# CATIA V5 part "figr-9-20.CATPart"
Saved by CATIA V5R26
Part number: Part3
Bounding box of the stored display mesh (mm): x -112 to 0, y -101.683 to 100, z -80.304 to 44.415
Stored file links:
  D:\_Deepak\CATIA\CATIA V5-6R2016_Deepak\Resources\Part files\Partfiles\c09_catia_v5_6r2016_prt\figr-9-20.CATPart
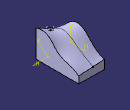
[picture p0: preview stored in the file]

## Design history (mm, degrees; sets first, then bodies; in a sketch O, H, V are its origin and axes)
Set1
  Plane1: type Offset, RefPlane yz-plane, Offset -112
  Plane2: type Offset, RefPlane yz-plane, Offset -63
  Plane3: type Normal, Curve Sketch4, RefPoint vertex of Sketch4
Body1 (main body)
  Sketch1 on yz-plane, origin (0, 0, 0), H (0, 1, 0), V (0, 0, 1)
    spline S1 through (-92.6897, 40.1119) (-30, 30) (10, -10) (60, -30) (97.3103, -50.3041)
    line L1 (97.3103, -50.3041) -> (97.3103, -80.3041)
    line L2 (97.3103, -80.3041) -> (-92.6897, -80.3041)
    line L3 (-92.6897, -80.3041) -> (-92.6897, 40.1119)
    point P3 (-92.6897, 40.1119)
    point P4 (97.3103, -50.3041)
    point P5 (-92.6897, 40.1119)
    point P6 (97.3103, -50.3041)
    vertical: L1 V, L3 V
    horizontal: L2 H
    coincidence: P5 P3, P6 P4
  Sketch2 on Plane1, origin (-112, 0, 0), H (0, 1, 0), V (0, 0, 1)
    spline S1 through (-90, -30) (-70, 10) (-20, 40) (40, 0) (100, -40)
    line L1 (100, -40) -> (100, -80)
    line L2 (100, -80) -> (-90, -80)
    line L3 (-90, -80) -> (-90, -30)
    point P3 (-90, -30)
    point P4 (100, -40)
    point P5 (40, 0)
    point P6 (-90, -30)
    point P7 (100, -40)
    coincidence: P5 H, P6 P3, P7 P4
    vertical: L1 V, L3 V
    horizontal: L2 H
  Loft1: Sections (Sketch1; Sketch2)
  Sketch3 on Plane3, origin (0, -40.1726, -44.9298), H (1, 0, 0), V (0, -0.7455, 0.6665)
    point P1 (-63, 68.4187)
    line L1 (-63, 68.4187) -> (-75.2117, 62.4925)
    line L2 (-75.2117, 62.4925) -> (-79.6266, 71.5898)
    line L3 (-79.6266, 71.5898) -> (-57.1205, 82.5119)
    line L4 (-57.1205, 82.5119) -> (-52.7056, 73.4145)
    point P5 (-52.7056, 73.4145)
    line L5 (-52.7056, 73.4145) -> (-63, 68.4187)
    reference projected point E1 (-63, 68.4187) from vertex of Sketch4
    perpendicularity: L2 L1
    parallelism: L3 L1, L4 L2, L5 L1
    coincidence: P5 L1, P1 E1
  Sketch4 on Plane2, origin (-63, 0, 0), H (0, 1, 0), V (0, 0, 1)
    intersected curve E1 from face of Loft1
